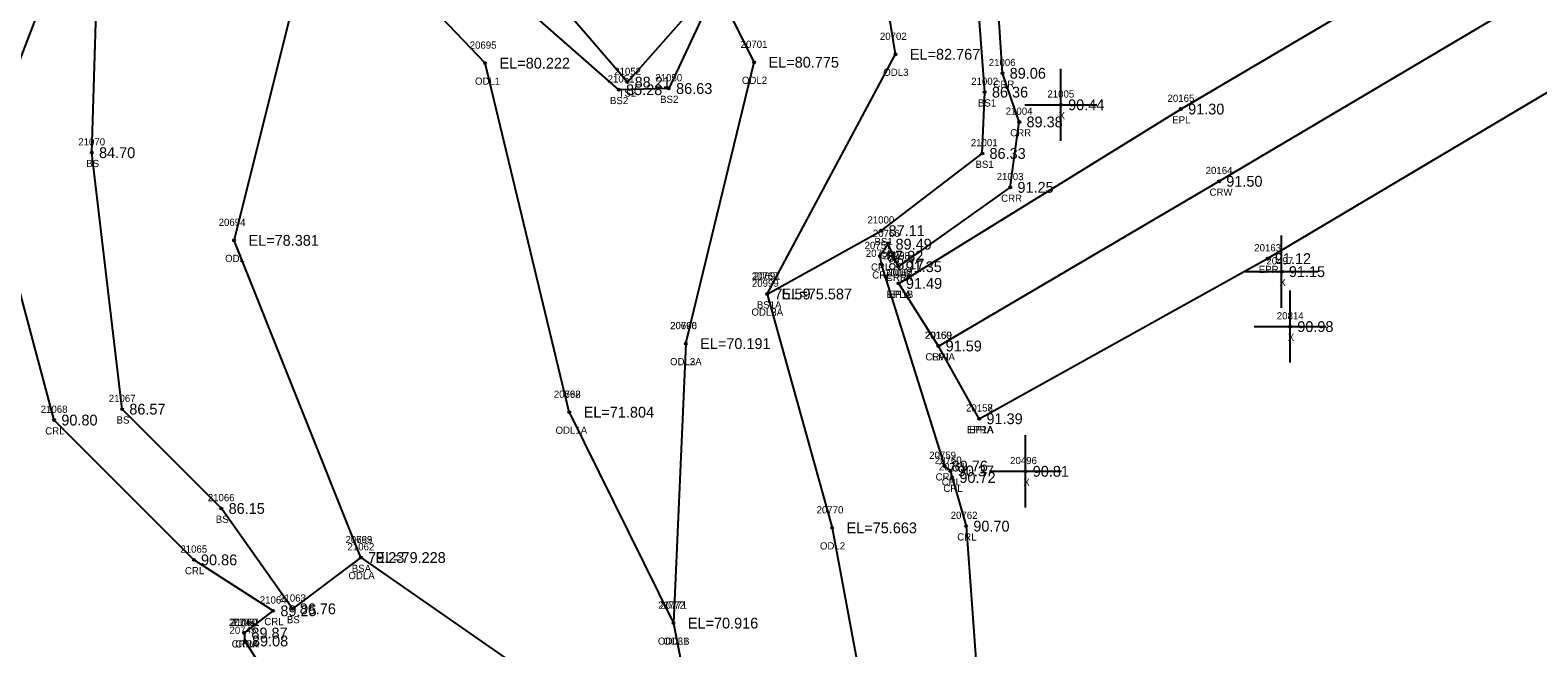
# Model space of a CAD drawing. Extents: x 2530197 to 2532051, y 935230 to 936631.
# Drawn here: x 2531049.2 to 2531258.3, y 935950.2 to 936035.9 of the extents above; entities that cross this region are included whole.
import ezdxf

# ---------------------------------------------------------------- set-up
doc = ezdxf.new("R2010")
doc.units = 0
for name, color, linetype in [('RD_DTM_BkLn1', 7, 'Continuous'), ('RD_DTM_BkLn2', 7, 'Continuous'), ('RD_DTM_BkLn_txCode', 7, 'Continuous'), ('RD_EX_H2O', 7, 'Continuous'), ('RD_EX_H2O_txCode', 7, 'Continuous'), ('RD_EX_Misc', 7, 'Continuous'), ('RD_EX_Misc_txCode', 7, 'Continuous'), ('RD_EX_Road', 7, 'Continuous'), ('RD_EX_Road_txCode', 7, 'Continuous'), ('RD_EX_TX_H2O_ELEV', 7, 'Continuous'), ('RD_EX_TX_Misc_ELEV', 7, 'Continuous'), ('RD_EX_TX_Road_ELEV', 7, 'Continuous'), ('RD_HC_Survey_ELEV', 7, 'Continuous'), ('RD_HC_Survey_txCode', 7, 'Continuous'), ('RD_SMD_Locator', 7, 'Continuous')]:
    doc.layers.add(name, color=color, linetype=linetype)

msp = doc.modelspace()

# ---------------------------------------------------------------- linework, layer by layer
at = {"layer": 'RD_DTM_BkLn1'}
msp.add_lwpolyline([(2531175.16, 935992.09), (2531214.08, 936014.93), (2531297.2, 936064.16), (2531382.2, 936114.3), (2531466.12, 936163.77), (2531548.89, 936212.96), (2531632.55, 936261.89), (2531678, 936289.19), (2531722.34, 936315.93), (2531754.26, 936342.49), (2531759.78, 936349.83), (2531772.77, 936373.29), (2531778.96, 936389.71), (2531793.78, 936438.29), (2531813.65, 936511.36), (2531832.39, 936582.88)], dxfattribs=at)
at = {"layer": 'RD_DTM_BkLn2'}
for points in [[(2531151.41, 935999.3), (2531167.24, 936008.08), (2531181.24, 936018.79), (2531181.58, 936027.3), (2531178.12, 936073.45), (2531167.63, 936105.68), (2531166.35, 936111.09), (2531158.41, 936111.85), (2531152.62, 936122.31), (2531150.51, 936125.78), (2531152.42, 936137.74), (2531230.98, 936186.53), (2531313.57, 936233.84), (2531368.67, 936272.3), (2531431.6, 936307.72), (2531489.09, 936344.56)], [(2531091.86, 936098.94), (2531097.3, 936102.68), (2531108.56, 936098.95), (2531116.45, 936085.08), (2531113.3, 936079.49), (2531130.73, 936056.45), (2531143.61, 936040.3), (2531137.78, 936027.8), (2531130.84, 936027.63), (2531112.74, 936043.51)], [(2531095.07, 935962.75), (2531085.58, 935955.64), (2531075.72, 935969.56), (2531061.95, 935983.33), (2531057.75, 936018.9), (2531058.33, 936038.43), (2531082.75, 936047.59), (2531082.98, 936051.85), (2531069.38, 936060.72), (2531066.72, 936076.15), (2531063.39, 936087.66), (2531052.84, 936091.07)], [(2531114.62, 936085.33), (2531108.53, 936080.08), (2531109.84, 936073.89), (2531127.85, 936056.66), (2531140.52, 936038.24), (2531132.03, 936028.68), (2531114.82, 936048.67)]]:
    msp.add_lwpolyline(points, dxfattribs=at)
at = {"layer": 'RD_EX_H2O'}
msp.add_line((2531140.12, 935992.42), (2531138.41, 935953.66), dxfattribs=at)
for points in [[(2531078.88, 935952.28), (2531078.88, 935952.28), (2531082.9, 935955.37), (2531071.89, 935962.43), (2531052.52, 935981.82), (2531042.66, 936018.54), (2531050.4, 936038.59), (2531079.35, 936050.48), (2531076.46, 936052.29), (2531062.77, 936059.41), (2531060.27, 936060.12), (2531061.98, 936077.76), (2531053.99, 936081.48), (2531023.23, 936060.57), (2531009.04, 936063.64), (2530981.92, 936072.85), (2530952.28, 936069.69), (2530922.53, 936086.42), (2530896.36, 936118.01), (2530886.54, 936120.09), (2530870.44, 936126.5), (2530844.88, 936119.11), (2530827.4, 936131.93), (2530794.88, 936161.74)], [(2531169.61, 936003.09), (2531185.12, 936014.09), (2531186.37, 936023.16), (2531184.04, 936029.91), (2531181.18, 936073.98), (2531171.96, 936106.16), (2531168.92, 936112.88), (2531161.58, 936114.63), (2531156.28, 936123.52), (2531154.46, 936124.24), (2531153.17, 936127.08), (2531152.81, 936126.44), (2531153.52, 936135.49)], [(2531123.96, 935982.91), (2531112.3, 936031.32), (2531095.21, 936049.23), (2531090.66, 936054.69), (2531088.09, 936058.64), (2531088.19, 936104.76)], [(2531151.41, 935999.3), (2531169.2, 936032.55), (2531157.31, 936105.83)], [(2531095.07, 935962.75), (2531077.48, 936006.74), (2531086.98, 936044.62), (2531085.89, 936051.59), (2531084.72, 936053.27), (2531083.78, 936058.53), (2531072.15, 936098.25)], [(2531140.12, 935992.42), (2531149.6, 936031.44), (2531122.92, 936085.04)], [(2531169.61, 936003.09), (2531168.21, 936006.21), (2531167.04, 936004.54), (2531167.21, 936003.45), (2531176, 935975.44), (2531176.84, 935974.76), (2531177.07, 935973.85), (2531179, 935967.11), (2531180.39, 935948.02), (2531175.92, 935941.33), (2531173.5, 935933.2), (2531181.71, 935892.9), (2531201.16, 935775.97), (2531215.24, 935672.42), (2531231.54, 935569.22), (2531229.65, 935447.9)], [(2531151.41, 935999.3), (2531160.42, 935966.87), (2531174.33, 935892.02), (2531192.74, 935775.85), (2531209.3, 935672.4), (2531227.01, 935569.99), (2531223.19, 935447.63)], [(2531123.96, 935982.91), (2531138.41, 935953.66), (2531150.01, 935894.11), (2531170.89, 935766.15), (2531194.87, 935668.24), (2531198.82, 935567.24), (2531215.76, 935447.86)], [(2531095.07, 935962.75), (2531122.05, 935944.01), (2531139.42, 935896.32), (2531161, 935756.43), (2531179.99, 935655.36), (2531191.29, 935570.65), (2531207.98, 935448.59)], [(2531078.88, 935952.28), (2531078.96, 935951.18), (2531094.18, 935926.97), (2531103.29, 935929.49), (2531106.67, 935929.67), (2531109.75, 935927.85), (2531109.94, 935928.67), (2531111.53, 935928.19), (2531109.98, 935924.15), (2531114.47, 935921.71), (2531121.2, 935920.45), (2531134.65, 935891.6), (2531155.43, 935754.46), (2531173.73, 935652.91), (2531186.19, 935572.51), (2531201.43, 935446.7)]]:
    msp.add_lwpolyline(points, dxfattribs=at)
at = {"layer": 'RD_EX_Misc'}
for p, q in [((2531192.15, 936020.54), (2531192.15, 936030.54)), ((2531187.15, 936025.54), (2531197.15, 936025.54)), ((2531222.76, 935997.4), (2531222.76, 936007.4)), ((2531217.76, 936002.4), (2531227.76, 936002.4)), ((2531223.93, 935989.78), (2531223.93, 935999.78)), ((2531218.93, 935994.78), (2531228.93, 935994.78)), ((2531187.24, 935969.71), (2531187.24, 935979.71)), ((2531182.24, 935974.71), (2531192.24, 935974.71))]:
    msp.add_line(p, q, dxfattribs=at)
at = {"layer": 'RD_EX_Road'}
for points in [[(2531169.65, 936000.77), (2531208.79, 936024.95), (2531292.04, 936074.02), (2531376.24, 936123.7), (2531460.37, 936174.49), (2531542.92, 936223.44), (2531626.67, 936270.85), (2531672.4, 936298.39), (2531714.28, 936327.21), (2531747.19, 936360.45), (2531761.42, 936377.32), (2531773.11, 936411.11), (2531782.2, 936441.65), (2531803.17, 936514.76), (2531820.28, 936585.8)], [(2531180.82, 935982), (2531220.82, 936004.21), (2531303.54, 936053.39), (2531388.75, 936103.71), (2531472.27, 936152.98), (2531554.79, 936201.9), (2531638.11, 936250.92), (2531683.19, 936278.28), (2531730.37, 936304.55), (2531771.5, 936341.26), (2531788.67, 936375.53), (2531805.57, 936434.84), (2531825.53, 936508.74), (2531844.13, 936579.65)], [(2531180.82, 935982), (2531175.16, 935992.09), (2531169.65, 936000.77)]]:
    msp.add_lwpolyline(points, dxfattribs=at)
at = {"layer": 'RD_SMD_Locator'}
for centre in [(2531112.3, 936031.32), (2531149.6, 936031.44), (2531169.2, 936032.55), (2531132.03, 936028.68), (2531184.04, 936029.91), (2531130.84, 936027.63), (2531137.78, 936027.8), (2531181.58, 936027.3), (2531192.15, 936025.54), (2531208.79, 936024.95), (2531186.37, 936023.16), (2531057.75, 936018.9), (2531181.24, 936018.79), (2531185.12, 936014.09), (2531214.08, 936014.93), (2531167.24, 936008.08), (2531077.48, 936006.74), (2531168.21, 936006.21), (2531167.04, 936004.54), (2531167.21, 936003.45), (2531220.82, 936004.21), (2531169.61, 936003.09), (2531169.61, 936003.09), (2531222.76, 936002.4), (2531151.41, 935999.3), (2531151.41, 935999.3), (2531151.41, 935999.3), (2531169.65, 936000.77), (2531169.65, 936000.77), (2531223.93, 935994.78), (2531140.12, 935992.42), (2531140.12, 935992.42), (2531175.16, 935992.09), (2531175.16, 935992.09), (2531061.95, 935983.33), (2531123.96, 935982.91), (2531123.96, 935982.91), (2531052.52, 935981.82), (2531180.82, 935982), (2531180.82, 935982), (2531176, 935975.44), (2531176.84, 935974.76), (2531187.24, 935974.71), (2531177.07, 935973.85), (2531075.72, 935969.56), (2531160.42, 935966.87), (2531179, 935967.11), (2531071.89, 935962.43), (2531095.07, 935962.75), (2531095.07, 935962.75), (2531095.07, 935962.75), (2531082.9, 935955.37), (2531085.58, 935955.64), (2531138.41, 935953.66), (2531138.41, 935953.66), (2531078.88, 935952.28), (2531078.88, 935952.28), (2531078.88, 935952.28), (2531078.96, 935951.18)]:
    msp.add_circle(centre, 0.15, dxfattribs=at)

# ---------------------------------------------------------------- texts
at = {"layer": 'RD_DTM_BkLn_txCode'}
for s, p in [('21052', (2531130.2, 936029.68)), ('21051', (2531129.29, 936028.63)), ('21050', (2531135.91, 936028.8)), ('21002', (2531179.71, 936028.3)), ('BS2', (2531129.61, 936025.63)), ('TS2', (2531130.79, 936026.68)), ('BS2', (2531136.56, 936025.8)), ('BS1', (2531180.64, 936025.3)), ('21070', (2531055.87, 936019.9)), ('21001', (2531179.65, 936019.79)), ('BS', (2531056.97, 936016.9)), ('BS1', (2531180.3, 936016.79)), ('21000', (2531165.32, 936009.08)), ('BS1', (2531166.29, 936006.08)), ('20999', (2531149.29, 936000.3)), ('BS1A', (2531149.98, 935997.3)), ('21067', (2531060.1, 935984.33)), ('BS', (2531061.18, 935981.33)), ('21066', (2531073.83, 935970.56)), ('BS', (2531074.94, 935967.56)), ('21062', (2531093.21, 935963.75)), ('BSA', (2531093.8, 935960.75)), ('21063', (2531083.72, 935956.64)), ('BS', (2531084.8, 935953.64))]:
    msp.add_text(s, height=1, dxfattribs=at).set_placement(p)
at = {"layer": 'RD_EX_H2O_txCode'}
for s, p in [('20702', (2531167.04, 936034.55)), ('20695', (2531110.16, 936033.32)), ('20701', (2531147.73, 936033.44)), ('21006', (2531182.14, 936030.91)), ('ODL1', (2531110.89, 936028.32)), ('ODL2', (2531147.91, 936028.44)), ('ODL3', (2531167.51, 936029.55)), ('CRR', (2531182.79, 936027.91)), ('21004', (2531184.49, 936024.16)), ('CRR', (2531185.12, 936021.16)), ('21003', (2531183.24, 936015.09)), ('CRR', (2531183.86, 936012.09)), ('20694', (2531075.34, 936008.74)), ('20756', (2531166.07, 936007.21)), ('20757', (2531164.92, 936005.54)), ('ODL', (2531076.23, 936003.74)), ('20758', (2531165.09, 936004.45)), ('CRL', (2531165.81, 936002.54)), ('CRL', (2531166.98, 936004.21)), ('20755', (2531167.49, 936004.09)), ('20998', (2531167.49, 936004.09)), ('20767', (2531149.27, 936001.3)), ('20691', (2531149.55, 936001.3)), ('CRL', (2531165.98, 936001.45)), ('CRRA', (2531167.87, 936001.09)), ('CRLA', (2531167.89, 936001.09)), ('ODL3A', (2531149.23, 935996.3)), ('ODL2A', (2531149.23, 935996.3)), ('20690', (2531137.94, 935994.42)), ('20766', (2531137.96, 935994.42)), ('ODL2A', (2531137.94, 935989.42)), ('ODL3A', (2531137.94, 935989.42)), ('20692', (2531121.82, 935984.91)), ('20768', (2531121.82, 935984.91)), ('21068', (2531050.66, 935982.82)), ('CRL', (2531051.29, 935979.82)), ('ODL1A', (2531122.06, 935979.91)), ('ODL1A', (2531122.06, 935979.91)), ('20759', (2531173.88, 935976.44)), ('20760', (2531174.66, 935975.76)), ('CRL', (2531174.77, 935973.44)), ('20761', (2531175.21, 935974.85)), ('CRL', (2531175.61, 935972.76)), ('CRL', (2531175.84, 935971.85)), ('20770', (2531158.26, 935968.87)), ('20762', (2531176.86, 935968.11)), ('CRL', (2531177.77, 935965.11)), ('21065', (2531070.03, 935963.43)), ('20693', (2531092.93, 935964.75)), ('20769', (2531092.93, 935964.75)), ('ODL2', (2531158.73, 935963.87)), ('CRL', (2531070.66, 935960.43)), ('ODLA', (2531093.34, 935959.75)), ('ODLA', (2531093.34, 935959.75)), ('21064', (2531081.04, 935956.37)), ('20772', (2531136.29, 935955.66)), ('20771', (2531136.58, 935955.66)), ('20744', (2531076.76, 935953.28)), ('21060', (2531076.98, 935953.28)), ('21061', (2531077.3, 935953.28)), ('CRL', (2531081.67, 935953.37)), ('20745', (2531076.84, 935952.18)), ('CRRA', (2531077.14, 935950.28)), ('CRLA', (2531077.16, 935950.28)), ('CRL', (2531077.65, 935950.28)), ('ODL3B', (2531136.25, 935950.66)), ('ODL1', (2531137, 935950.66))]:
    msp.add_text(s, height=1, dxfattribs=at).set_placement(p)
at = {"layer": 'RD_EX_Misc_txCode'}
for s, p in [('21005', (2531190.27, 936026.54)), ('X', (2531191.83, 936023.54)), ('20497', (2531220.64, 936003.4)), ('X', (2531222.44, 936000.4)), ('20814', (2531222.09, 935995.78)), ('X', (2531223.61, 935992.78)), ('20496', (2531185.1, 935975.71)), ('X', (2531186.93, 935972.71))]:
    msp.add_text(s, height=1, dxfattribs=at).set_placement(p)
at = {"layer": 'RD_EX_Road_txCode'}
for s, p in [('20165', (2531206.93, 936025.95)), ('EPL', (2531207.59, 936022.95)), ('20163', (2531218.96, 936005.21)), ('20162', (2531167.79, 936001.77)), ('20161', (2531168.07, 936001.77)), ('EPR', (2531219.59, 936002.21)), ('EPLA', (2531167.96, 935998.77)), ('EP1B', (2531168.25, 935998.77)), ('20159', (2531173.33, 935993.09)), ('EP1', (2531174.24, 935990.09)), ('20157', (2531178.99, 935983)), ('20158', (2531178.99, 935983)), ('EPRA', (2531179.11, 935980)), ('EP1A', (2531179.41, 935980))]:
    msp.add_text(s, height=1, dxfattribs=at).set_placement(p)
at = {"layer": 'RD_EX_TX_H2O_ELEV'}
for s, p in [('EL=82.767', (2531171.2, 936031.8)), ('EL=80.222', (2531114.3, 936030.57)), ('EL=80.775', (2531151.6, 936030.69)), ('89.06', (2531185.04, 936029.16)), ('89.38', (2531187.37, 936022.41)), ('91.25', (2531186.12, 936013.34)), ('EL=78.381', (2531079.48, 936005.99)), ('89.49', (2531169.21, 936005.46)), ('87.82', (2531168.04, 936003.79)), ('88.17', (2531168.21, 936002.7)), ('91.35', (2531170.61, 936002.34)), ('91.35', (2531170.61, 936002.34)), ('EL=75.587', (2531153.41, 935998.55)), ('EL=75.587', (2531153.41, 935998.55)), ('EL=70.191', (2531142.12, 935991.67)), ('EL=70.191', (2531142.12, 935991.67)), ('EL=71.804', (2531125.96, 935982.16)), ('EL=71.804', (2531125.96, 935982.16)), ('90.80', (2531053.52, 935981.07)), ('89.76', (2531177, 935974.69)), ('90.37', (2531177.84, 935974.01)), ('90.72', (2531178.07, 935973.1)), ('EL=75.663', (2531162.42, 935966.12)), ('90.70', (2531180, 935966.36)), ('90.86', (2531072.89, 935961.68)), ('EL=79.228', (2531097.07, 935962)), ('EL=79.228', (2531097.07, 935962)), ('89.25', (2531083.9, 935954.62)), ('EL=70.916', (2531140.41, 935952.91)), ('EL=70.916', (2531140.41, 935952.91)), ('89.87', (2531079.88, 935951.53)), ('89.87', (2531079.88, 935951.53)), ('89.87', (2531079.88, 935951.53)), ('89.08', (2531079.96, 935950.43))]:
    msp.add_text(s, height=1.5, dxfattribs=at).set_placement(p)
at = {"layer": 'RD_EX_TX_Misc_ELEV'}
for s, p in [('88.21', (2531133.03, 936027.93)), ('85.28', (2531131.84, 936026.88)), ('86.63', (2531138.78, 936027.05)), ('86.36', (2531182.58, 936026.55)), ('90.44', (2531193.15, 936024.79)), ('84.70', (2531058.75, 936018.15)), ('86.33', (2531182.24, 936018.04)), ('87.11', (2531168.24, 936007.33)), ('91.15', (2531223.76, 936001.65)), ('75.59', (2531152.41, 935998.55)), ('90.98', (2531224.93, 935994.03)), ('86.57', (2531062.95, 935982.58)), ('90.81', (2531188.24, 935973.96)), ('86.15', (2531076.72, 935968.81)), ('79.23', (2531096.07, 935962)), ('86.76', (2531086.58, 935954.89))]:
    msp.add_text(s, height=1.5, dxfattribs=at).set_placement(p)
at = {"layer": 'RD_EX_TX_Road_ELEV'}
for s, p in [('91.30', (2531209.79, 936024.2)), ('91.12', (2531221.82, 936003.46)), ('91.49', (2531170.65, 936000.02)), ('91.49', (2531170.65, 936000.02)), ('91.59', (2531176.16, 935991.34)), ('91.39', (2531181.82, 935981.25)), ('91.39', (2531181.82, 935981.25))]:
    msp.add_text(s, height=1.5, dxfattribs=at).set_placement(p)
at = {"layer": 'RD_HC_Survey_ELEV'}
for s, p in [('91.50', (2531215.08, 936014.18)), ('91.59', (2531176.16, 935991.34))]:
    msp.add_text(s, height=1.5, dxfattribs=at).set_placement(p)
at = {"layer": 'RD_HC_Survey_txCode'}
for s, p in [('20164', (2531212.22, 936015.93)), ('CRW', (2531212.76, 936012.93)), ('20160', (2531173.26, 935993.09)), ('CRWA', (2531173.36, 935990.09))]:
    msp.add_text(s, height=1, dxfattribs=at).set_placement(p)

doc.saveas('drawing.dxf')
